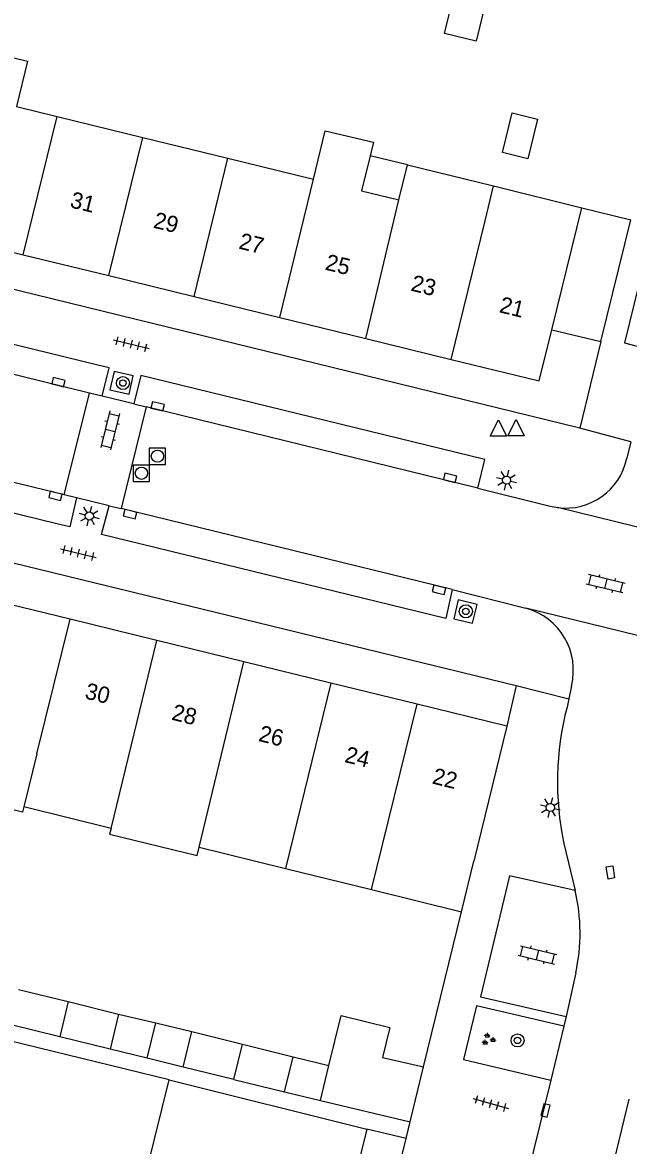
# Model space of a CAD drawing. Extents: x 128000 to 131008, y 398996 to 402500.
# Drawn here: x 128391.4 to 128428.5, y 399231.8 to 399300.6 of the extents above; entities that cross this region are included whole.
import ezdxf

# ---------------------------------------------------------------- set-up
doc = ezdxf.new("R2010")
doc.units = 0
for name, color, linetype in [('gg-afsc-erfafscheiding', 7, 'Continuous'), ('gg-afsc-muur', 7, 'Continuous'), ('gg-anno-huisnummerreeks BGT', 7, 'Continuous'), ('gg-bbg-bijgebouw', 7, 'Continuous'), ('gg-bbg-gedigitaliseerde bebouwing', 7, 'Continuous'), ('gg-bbg-gedigitaliseerde bijgebouw', 7, 'Continuous'), ('gg-bbg-hoofdgebouw', 7, 'Continuous'), ('gg-bbg-luifel en loopbrug', 7, 'Continuous'), ('gg-bbg-tussenscheiding', 7, 'Continuous'), ('gg-knt-verharding', 7, 'Continuous'), ('gg-knt-verharding nz', 7, 'Continuous'), ('gt-grn-weggrens', 7, 'Continuous'), ('gt-symb-boom', 7, 'Continuous'), ('gt-symb-groenvak', 7, 'Continuous'), ('gt-symb-klinker verharding', 7, 'Continuous'), ('gt-symb-kolk', 7, 'Continuous'), ('gt-symb-kolk center center', 7, 'Continuous'), ('gt-symb-lichtmast', 7, 'Continuous'), ('gt-symb-rioolschacht', 7, 'Continuous'), ('gt-symb-tegel verharding', 7, 'Continuous'), ('gt-symb-waterafsluiter', 7, 'Continuous')]:
    doc.layers.add(name, color=color, linetype=linetype)

# ---------------------------------------------------------------- blocks, each defined once
blk = doc.blocks.new('gt0-KL1')
at = {"layer": 'gt-symb-klinker verharding'}
for p, q in [((-1.15, 0.3), (1.15, 0.3)), ((-1, -0.3), (-1, 0.3)), ((-0.5, 0.3), (-0.5, 0.45)), ((0, -0.3), (0, 0.3)), ((0.5, 0.3), (0.5, 0.45)), ((1, -0.3), (1, 0.3)), ((-1.15, -0.3), (1.15, -0.3)), ((-0.5, -0.45), (-0.5, -0.3)), ((0.5, -0.45), (0.5, -0.3))]:
    blk.add_line(p, q, dxfattribs=at)
blk = doc.blocks.new('gt0-KOLKCC')
at = {"layer": 'gt-symb-kolk center center'}
blk.add_lwpolyline([(-0.375, 0.2), (0.375, 0.2), (0.375, -0.2), (-0.375, -0.2)], close=True, dxfattribs=at)
blk = doc.blocks.new('gt0-GRVAK')
at = {"layer": 'gt-symb-groenvak'}
for p, q in [((-0.11, 0.189), (-0.228, 0.24)), ((-0.182, 0.153), (0.088, 0.153)), ((-0.091, 0.211), (-0.156, 0.322)), ((-0.047, 0.214), (-0.047, 0.393)), ((-0.004, 0.211), (0.061, 0.322)), ((0.015, 0.189), (0.133, 0.24)), ((0.262, -0.052), (0.197, 0.059)), ((0.305, -0.049), (0.305, 0.13)), ((0.349, -0.052), (0.414, 0.059)), ((-0.245, -0.228), (-0.363, -0.177)), ((-0.318, -0.264), (-0.047, -0.264)), ((-0.226, -0.206), (-0.291, -0.095)), ((-0.183, -0.203), (-0.183, -0.024)), ((-0.139, -0.206), (-0.074, -0.095)), ((-0.12, -0.228), (-0.002, -0.177)), ((0.243, -0.074), (0.125, -0.023)), ((0.17, -0.11), (0.441, -0.11)), ((0.368, -0.074), (0.486, -0.023))]:
    blk.add_line(p, q, dxfattribs=at)
blk = doc.blocks.new('gt0-TEG1')
at = {"layer": 'gt-symb-tegel verharding'}
for p, q in [((-1.125, 0), (1.125, 0)), ((-0.9, -0.25), (-0.9, 0.25)), ((-0.45, -0.25), (-0.45, 0.25)), ((0, -0.25), (0, 0.25)), ((0.45, -0.25), (0.45, 0.25)), ((0.9, -0.25), (0.9, 0.25))]:
    blk.add_line(p, q, dxfattribs=at)
blk = doc.blocks.new('gt0-BOOM')
at = {"layer": 'gt-symb-boom'}
for radius in [0.4, 0.2]:
    blk.add_circle((0, 0), radius, dxfattribs=at)
blk = doc.blocks.new('gt0-KOLK')
at = {"layer": 'gt-symb-kolk'}
blk.add_lwpolyline([(0, 0), (0.375, 0), (0.375, 0.4), (-0.375, 0.4), (-0.375, 0), (0, 0)], dxfattribs=at)
blk = doc.blocks.new('gt0-LMAST')
at = {"layer": 'gt-symb-lichtmast'}
for p, q in [((-0.182, 0.173), (-0.447, 0.438)), ((-0.005, 0.246), (-0.005, 0.621)), ((0.172, 0.173), (0.437, 0.438)), ((-0.255, -0.004), (-0.63, -0.004)), ((-0.182, -0.181), (-0.447, -0.446)), ((-0.005, -0.254), (-0.005, -0.629)), ((0.437, -0.446), (0.172, -0.181)), ((0.245, -0.004), (0.62, -0.004))]:
    blk.add_line(p, q, dxfattribs=at)
blk.add_circle((-0.005, -0.004), 0.25, dxfattribs=at)
blk = doc.blocks.new('gt0-RS')
at = {"layer": 'gt-symb-rioolschacht'}
blk.add_lwpolyline([(-0.5, -0.5), (0.5, -0.5), (0.5, 0.5), (-0.5, 0.5)], close=True, dxfattribs=at)
blk.add_circle((0, 0), 0.375, dxfattribs=at)
blk = doc.blocks.new('gt0-WAFSL')
at = {"layer": 'gt-symb-waterafsluiter'}
for p, q in [((-0.5, -0.333), (0, 0.667)), ((0, 0.667), (0.5, -0.333)), ((0.5, -0.333), (-0.5, -0.333))]:
    blk.add_line(p, q, dxfattribs=at)

msp = doc.modelspace()

# ---------------------------------------------------------------- linework, layer by layer
at = {"layer": 'gg-afsc-erfafscheiding'}
msp.add_lwpolyline([(128400.367, 399235.799), (128373.581, 399242.325), (128374.263, 399238.846)], dxfattribs=at)
at = {"layer": 'gg-afsc-muur'}
msp.add_line((128415.947, 399236.594), (128418.272, 399246.1), dxfattribs=at)
at = {"layer": 'gg-bbg-bijgebouw'}
for p, q in [((128426.82, 399281.02), (128428.65, 399288.48)), ((128423.8, 399281.74), (128426.82, 399281.02)), ((128415.125, 399233.229), (128415.947, 399236.594))]:
    msp.add_line(p, q, dxfattribs=at)
msp.add_lwpolyline([(128413.888, 399239.009), (128413.441, 399237.169), (128415.947, 399236.594)], dxfattribs=at)
at = {"layer": 'gg-bbg-gedigitaliseerde bebouwing'}
for p, q in [((128393.499, 399294.805), (128398.752, 399293.523)), ((128398.752, 399293.523), (128403.957, 399292.253)), ((128403.957, 399292.253), (128409.213, 399290.97)), ((128414.444, 399289.693), (128414.961, 399291.843)), ((128414.961, 399291.843), (128420.231, 399290.548)), ((128420.231, 399290.548), (128425.64, 399289.218)), ((128396.799, 399251.204), (128391.457, 399252.513)), ((128399.003, 399230.35), (128400.367, 399235.799))]:
    msp.add_line(p, q, dxfattribs=at)
for points in [[(128388.226, 399296.091), (128388.904, 399298.87), (128391.683, 399298.192), (128391.005, 399295.413), (128393.499, 399294.805)], [(128409.213, 399290.97), (128409.916, 399293.934), (128412.88, 399293.232), (128412.679, 399292.385)], [(128412.679, 399292.385), (128412.152, 399290.246), (128414.444, 399289.693)], [(128391.457, 399252.513), (128391.382, 399252.205), (128386.098, 399253.497), (128386.496, 399255.124)], [(128396.799, 399251.204), (128396.712, 399250.848), (128402.079, 399249.534), (128402.205, 399250.051)]]:
    msp.add_lwpolyline(points, dxfattribs=at)
at = {"layer": 'gg-bbg-gedigitaliseerde bijgebouw'}
for p, q in [((128425.64, 399289.218), (128428.65, 399288.48)), ((128391.119, 399241.338), (128394.175, 399240.59)), ((128394.175, 399240.59), (128397.263, 399239.834)), ((128397.263, 399239.834), (128396.736, 399237.679)), ((128396.736, 399237.679), (128393.67, 399238.429)), ((128401.211, 399236.584), (128401.744, 399238.758)), ((128401.744, 399238.758), (128404.85, 399237.987)), ((128404.85, 399237.987), (128407.956, 399237.217)), ((128407.427, 399235.062), (128407.956, 399237.217)), ((128404.319, 399235.823), (128401.211, 399236.584)), ((128409.63, 399234.537), (128410.153, 399236.69)), ((128404.319, 399235.823), (128407.427, 399235.062)), ((128409.63, 399234.537), (128415.125, 399233.229))]:
    msp.add_line(p, q, dxfattribs=at)
for points in [[(128419.765, 399301.848), (128419.178, 399299.418), (128417.234, 399299.888), (128417.821, 399302.318), (128419.765, 399301.848)], [(128420.789, 399292.599), (128421.385, 399295.027), (128422.939, 399294.645), (128422.343, 399292.218), (128420.789, 399292.599)], [(128410.153, 399236.69), (128410.894, 399239.737), (128413.888, 399239.009)], [(128393.67, 399238.429), (128390.591, 399239.183), (128390.598, 399239.211)]]:
    msp.add_lwpolyline(points, dxfattribs=at)
at = {"layer": 'gg-bbg-hoofdgebouw'}
for p, q in [((128386.167, 399287.62), (128391.414, 399286.338)), ((128391.414, 399286.338), (128396.661, 399285.055)), ((128396.661, 399285.055), (128401.898, 399283.775)), ((128401.898, 399283.775), (128407.146, 399282.492)), ((128407.146, 399282.492), (128412.402, 399281.208)), ((128412.402, 399281.208), (128417.649, 399279.925)), ((128394.289, 399264.012), (128388.969, 399265.315)), ((128399.608, 399262.71), (128394.289, 399264.012)), ((128404.928, 399261.407), (128399.608, 399262.71)), ((128410.259, 399260.102), (128404.928, 399261.407)), ((128415.55, 399258.807), (128410.259, 399260.102)), ((128421.05, 399257.46), (128415.55, 399258.807)), ((128421.05, 399257.46), (128419.03, 399249.2)), ((128402.205, 399250.051), (128407.492, 399248.751)), ((128418.272, 399246.1), (128419.03, 399249.2)), ((128407.492, 399248.751), (128412.762, 399247.455)), ((128412.762, 399247.455), (128418.272, 399246.1)), ((128400.367, 399235.799), (128412.47, 399232.79)), ((128412.47, 399232.79), (128411.135, 399227.313))]:
    msp.add_line(p, q, dxfattribs=at)
msp.add_lwpolyline([(128417.649, 399279.925), (128423.03, 399278.61), (128423.8, 399281.74)], dxfattribs=at)
at = {"layer": 'gg-bbg-luifel en loopbrug'}
for p, q in [((128414.961, 399291.843), (128412.679, 399292.385)), ((128397.263, 399239.834), (128399.547, 399239.285)), ((128399.021, 399237.139), (128399.547, 399239.285)), ((128399.547, 399239.285), (128401.744, 399238.758)), ((128399.021, 399237.139), (128396.736, 399237.679)), ((128401.211, 399236.584), (128399.021, 399237.139)), ((128407.956, 399237.217), (128410.153, 399236.69)), ((128407.427, 399235.062), (128409.63, 399234.537))]:
    msp.add_line(p, q, dxfattribs=at)
at = {"layer": 'gg-bbg-tussenscheiding'}
for p, q in [((128391.414, 399286.338), (128393.499, 399294.805)), ((128396.661, 399285.055), (128398.752, 399293.523)), ((128401.898, 399283.775), (128403.957, 399292.253)), ((128407.146, 399282.492), (128409.213, 399290.97)), ((128419.716, 399288.407), (128420.231, 399290.548)), ((128412.402, 399281.208), (128414.444, 399289.693)), ((128423.8, 399281.74), (128425.64, 399289.218)), ((128417.649, 399279.925), (128419.716, 399288.407)), ((128392.255, 399255.768), (128394.289, 399264.012)), ((128396.799, 399251.204), (128399.608, 399262.71)), ((128402.205, 399250.051), (128404.928, 399261.407)), ((128410.259, 399260.102), (128407.492, 399248.751)), ((128412.762, 399247.455), (128415.55, 399258.807)), ((128392.255, 399255.768), (128391.457, 399252.513)), ((128394.175, 399240.59), (128393.67, 399238.429)), ((128404.319, 399235.823), (128404.85, 399237.987))]:
    msp.add_line(p, q, dxfattribs=at)
at = {"layer": 'gg-knt-verharding'}
for p, q in [((128426.82, 399281.02), (128425.52, 399275.72)), ((128393.928, 399271.639), (128395.476, 399277.867)), ((128396.255, 399277.676), (128395.476, 399277.867)), ((128398.205, 399277.199), (128396.255, 399277.676)), ((128398.949, 399277.017), (128397.412, 399270.788)), ((128398.205, 399277.199), (128398.949, 399277.017)), ((128428.653, 399274.886), (128428.4, 399273.873)), ((128394.69, 399271.453), (128393.928, 399271.639)), ((128396.68, 399270.967), (128394.69, 399271.453)), ((128396.68, 399270.967), (128397.412, 399270.788)), ((128417.694, 399265.829), (128422.212, 399264.685)), ((128421.63, 399259.95), (128421.05, 399257.46)), ((128425.008, 399259.923), (128424.845, 399259.128)), ((128424.845, 399259.128), (128424.74, 399258.62)), ((128424.54, 399250.282), (128425.23, 399247.396)), ((128424.691, 399239.677), (128424.544, 399239.081)), ((128424.544, 399239.081), (128423.738, 399235.788)), ((128423.738, 399235.788), (128422.248, 399229.684)), ((128425.914, 399223.824), (128428.55, 399234.622)), ((128414.875, 399232.204), (128412.47, 399232.79))]:
    msp.add_line(p, q, dxfattribs=at)
for points in [[(128434.768, 399299.874), (128433.018, 399300.303), (128428.262, 399280.935), (128430.044, 399280.463)], [(128425.52, 399275.72), (128372.06, 399288.8), (128372.12, 399289.049)], [(128395.907, 399279.602), (128375.611, 399284.559), (128375.193, 399282.828)], [(128396.255, 399277.676), (128396.687, 399279.412), (128395.907, 399279.602)], [(128396.981, 399279.188), (128396.73, 399278.052), (128397.902, 399277.793), (128398.153, 399278.929), (128396.981, 399279.188)], [(128399.378, 399278.756), (128398.625, 399278.939), (128398.205, 399277.199)], [(128419.273, 399272.045), (128419.706, 399273.804), (128399.378, 399278.756)], [(128393.486, 399269.863), (128373.208, 399274.82), (128373.661, 399276.595)], [(128367.54, 399270.57), (128368.17, 399272.98), (128421.63, 399259.95)], [(128419.273, 399272.045), (128423.632, 399270.957), (128424.159, 399270.85)], [(128394.69, 399271.453), (128394.27, 399269.671), (128393.486, 399269.863)], [(128396.973, 399269.008), (128396.209, 399269.194), (128396.68, 399270.967)], [(128417.694, 399265.829), (128417.308, 399264.051), (128396.973, 399269.008)], [(128417.796, 399264.029), (128418.947, 399263.761), (128419.238, 399264.91), (128418.074, 399265.204), (128417.796, 399264.029)], [(128425.23, 399247.396), (128421.205, 399248.299), (128419.434, 399240.878), (128424.691, 399239.677)], [(128424.544, 399239.081), (128419.194, 399240.328), (128418.405, 399237.039), (128423.738, 399235.788)], [(128401.058, 399182.005), (128402.51, 399181.63), (128414.875, 399232.204)]]:
    msp.add_lwpolyline(points, dxfattribs=at)
for centre, radius, start, end in [((128424.651, 399274.646), 3.828, 262.61407, 348.34874), ((128421.209, 399260.894), 3.921, 345.6579, 75.18061), ((128442.504, 399254.022), 18.35, 165.4899, 191.76197)]:
    msp.add_arc(centre, radius, start, end, dxfattribs=at)
at = {"layer": 'gg-knt-verharding nz'}
for p, q in [((128395.476, 399277.867), (128375.193, 399282.828)), ((128419.273, 399272.045), (128398.949, 399277.017)), ((128393.928, 399271.639), (128373.661, 399276.595)), ((128417.694, 399265.829), (128397.412, 399270.788)), ((128425.27, 399242.351), (128424.691, 399239.677))]:
    msp.add_line(p, q, dxfattribs=at)
msp.add_arc((128414.423, 399244.788), 11.117, 347.33878, 13.56976, dxfattribs=at)
at = {"layer": 'gt-grn-weggrens'}
for p, q in [((128428.653, 399274.886), (128425.52, 399275.72)), ((128435.878, 399267.972), (128424.159, 399270.85)), ((128433.85, 399261.836), (128422.212, 399264.685)), ((128421.63, 399259.95), (128424.845, 399259.128)), ((128414.875, 399232.204), (128415.125, 399233.229))]:
    msp.add_line(p, q, dxfattribs=at)

# ---------------------------------------------------------------- block references
at = {"layer": 'gt-symb-boom'}
for p in [(128397.53, 399278.479), (128418.541, 399264.495), (128421.708, 399238.218)]:
    msp.add_blockref('gt0-BOOM', p, dxfattribs=at)
at = {"layer": 'gt-symb-groenvak'}
msp.add_blockref('gt0-GRVAK', (128419.905, 399238.281), dxfattribs=at)
at = {"layer": 'gt-symb-klinker verharding'}
for p, rotation in [((128396.742, 399275.578), -103.93901435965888), ((128427.105, 399266.184), 166.22785456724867), ((128422.933, 399243.451), -13.480126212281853)]:
    msp.add_blockref('gt0-KL1', p, dxfattribs=dict(at, rotation=rotation))
at = {"layer": 'gt-symb-kolk'}
for p, rotation in [((128393.528, 399278.344), -13.74462955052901), ((128399.609, 399276.856), -13.74462955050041), ((128417.525, 399272.475), -13.772145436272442), ((128393.437, 399271.759), 166.25537044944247), ((128398.006, 399270.643), 166.26320909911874), ((128416.845, 399265.616), -13.772145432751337), ((128423.229, 399233.976), -103.70288996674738)]:
    msp.add_blockref('gt0-KOLK', p, dxfattribs=dict(at, rotation=rotation))
at = {"layer": 'gt-symb-kolk center center', "rotation": -80.79203094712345}
msp.add_blockref('gt0-KOLKCC', (128427.4, 399248.503), dxfattribs=at)
at = {"layer": 'gt-symb-lichtmast'}
for p, rotation in [((128421.041, 399272.535), -13.77214543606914), ((128395.471, 399270.336), -13.772145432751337), ((128423.72, 399252.482), -13.772145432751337)]:
    msp.add_blockref('gt0-LMAST', p, dxfattribs=dict(at, rotation=rotation))
at = {"layer": 'gt-symb-rioolschacht'}
for p in [(128399.64, 399273.999), (128398.661, 399272.954)]:
    msp.add_blockref('gt0-RS', p, dxfattribs=at)
at = {"layer": 'gt-symb-tegel verharding'}
for p, rotation in [((128398.051, 399280.856), -13.53585636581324), ((128394.804, 399268.066), -13.535856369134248), ((128420.063, 399234.358), -16.02410965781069)]:
    msp.add_blockref('gt0-TEG1', p, dxfattribs=dict(at, rotation=rotation))
at = {"layer": 'gt-symb-waterafsluiter'}
for p in [(128420.538, 399275.554), (128421.615, 399275.571)]:
    msp.add_blockref('gt0-WAFSL', p, dxfattribs=at)

# ---------------------------------------------------------------- texts
at = {"layer": 'gg-anno-huisnummerreeks BGT'}
for s, rotation, p in [('31', 346.2, (128394.235, 399289.251)), ('29', 346.3, (128399.338, 399288.003)), ('27', 346.3, (128404.577, 399286.722)), ('25', 346.3, (128409.867, 399285.429)), ('23', 346.2, (128415.119, 399284.147)), ('21', 346.3, (128420.536, 399282.822)), ('30', 346.2, (128395.141, 399259.171)), ('28', 346.2, (128400.459, 399257.868)), ('26', 346.2, (128405.785, 399256.564)), ('24', 346.2, (128411.06, 399255.273)), ('22', 346.2, (128416.425, 399253.959))]:
    msp.add_text(s, height=1, rotation=rotation, dxfattribs=at).set_placement(p)

doc.saveas('drawing.dxf')
